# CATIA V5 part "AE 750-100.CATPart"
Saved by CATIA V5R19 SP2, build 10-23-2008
Part number: AE 750-100
Bounding box of the stored display mesh (mm): x -24.865 to 24.865, y -24.997 to 24.997, z 0 to 250
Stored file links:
  C:\Users\Bora\Desktop\3D Katı model\AE serisi\AE 750\AE 750-100.CATPart
  C:\Program Files\Dassault Systemes\B19\intel_a\reffiles\standard\MetricThickPitch.txt
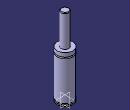
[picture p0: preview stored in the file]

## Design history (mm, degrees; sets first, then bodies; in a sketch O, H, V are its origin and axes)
Body1 (main body)
  Sketch1 on yz-plane, origin (0, 0, 0), H (0, 1, 0), V (0, 0, 1)
    point P1 (25, 132.5)
    point P8 (25, 136.5)
    point P9 (12.5, 248)
    point P11 (12.5, 248)
    point P13 (25, 136.5)
    point P14 (25, 132.5)
    line L1 (25, 132.5) -> (25, 8)
    line L2 (25, 4) -> (25, 0)
    line L3 (21.5, 8) -> (21.5, 4)
    line L4 (25, 149) -> (25, 136.5)
    line L5 (12.5, 248) -> (12.5, 149)
    arc A1 centre (10.5, 248) radius 2 from (12.5, 248) to (10.5, 250) ccw
    arc A2 centre (25, 134.5) radius 2 from (25, 136.5) to (25, 132.5) ccw
    line L6 (10.5, 250) -> (0, 250)
    point P15 (0, 250)
    line L7 (12.5, 149) -> (25, 149)
    line L8 (25, 0) -> (0, 0)
    line L9 (21.5, 8) -> (25, 8)
    line L10 (21.5, 4) -> (25, 4)
    coincidence: P15 V, P1 P14, P8 P13, P9 P11
    tangency: L6 A1
    horizontal: L7 H, L8 H, L9 H, L10 H
  Shaft1: profile Sketch1, axis Sketch1.V, angle 360
  Sketch2 on face of Shaft1 from Sketch1.L8, origin (0, 0, 0), H (1, 0, 0), V (0, -1, 0)
    point P1 (10, 0)
    distance P1 V = 10
  Hole1: placed by Sketch2, at (10, 0, 0) direction (0, 0, 1), diameter 6.647, depth 13, threaded "M8", thread diameter 8, thread depth 13, pitch 1.25
  CircPattern1: of Hole1, instances 2, angular step 180, axis from xy-plane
